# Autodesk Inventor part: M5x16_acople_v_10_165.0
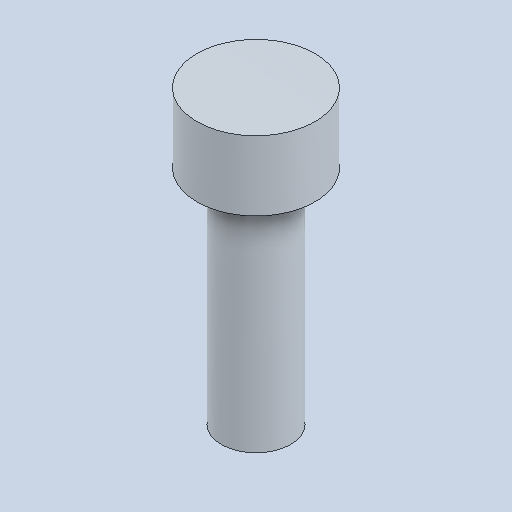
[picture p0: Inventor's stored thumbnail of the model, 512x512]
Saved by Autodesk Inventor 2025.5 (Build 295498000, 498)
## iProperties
Created: 2026-10
Part Number: M5x16_acople_v_10_165.0
Material: Genérico
Document SubType Name: Modeling
Designer: Luis M
Density: 1 g/cm^3
Appearance: Valor por defecto
Author: Luis M
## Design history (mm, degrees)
feature "Base1"
node "Sólido1"
